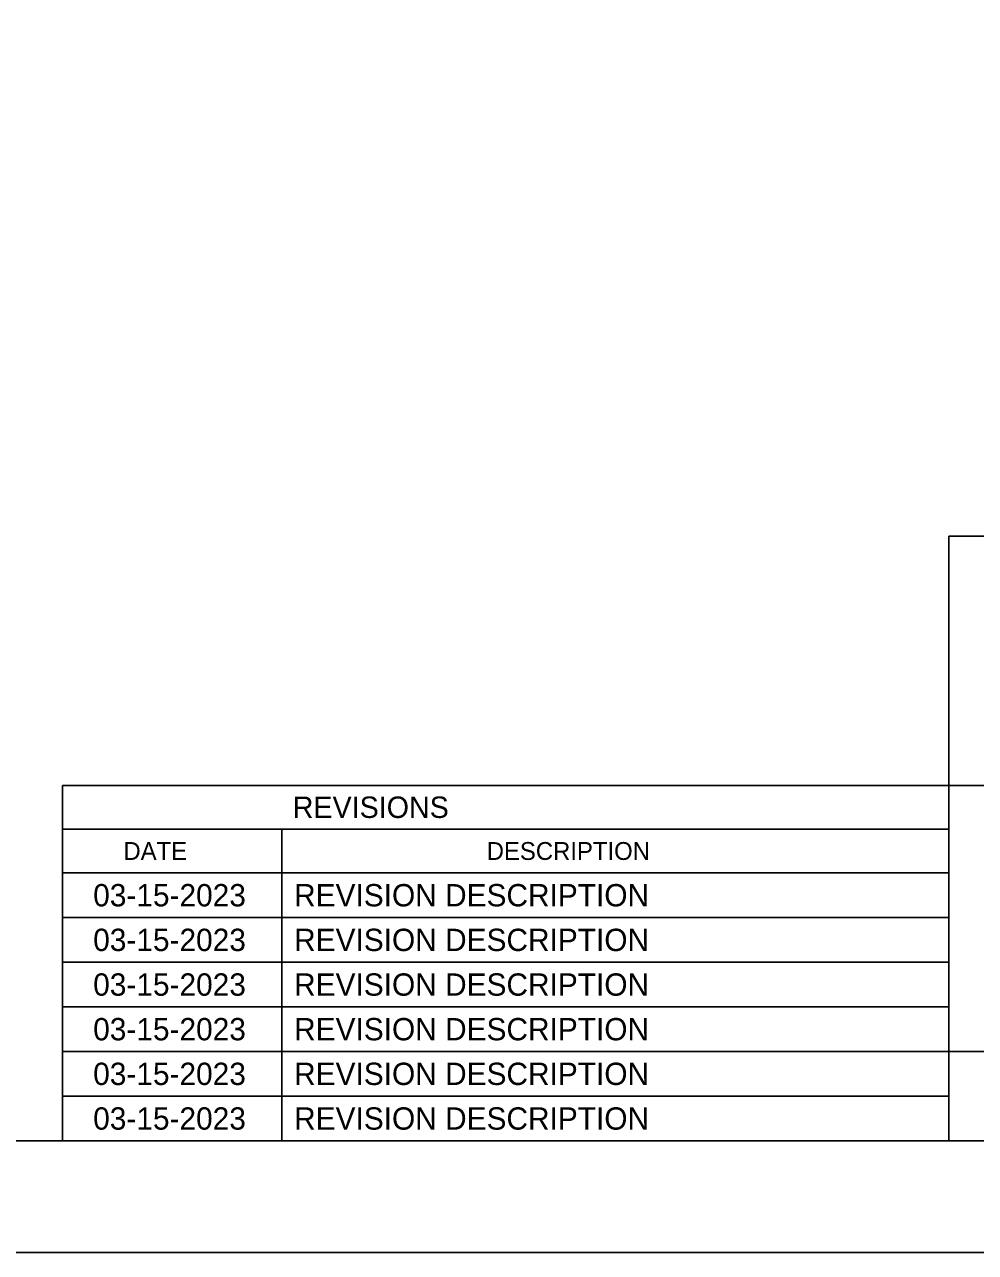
# Model space of a CAD drawing. Extents: x 0 to 2.83, y 0 to 1.83.
# Drawn here: x 2.0867 to 2.4416, y 0 to 0.4583 of the extents above; entities that cross this region are included whole.
import ezdxf

# ---------------------------------------------------------------- set-up
doc = ezdxf.new("R2010")
doc.units = 0
for name, color, linetype in [('SH_General_Details', 7, 'Continuous'), ('SH_General_Details_Sheet_Revision_Box-ILTollway', 7, 'Continuous'), ('SH_General_Details_Sheet_Revision_Text-ILTollway', 7, 'Continuous'), ('SH_Printer Plotting Border-ILTollway', 7, 'Continuous')]:
    doc.layers.add(name, color=color, linetype=linetype)

msp = doc.modelspace()

# ---------------------------------------------------------------- linework, layer by layer
at = {"layer": 'SH_General_Details'}
for p, q in [((2.43167, 0.04167), (2.43167, 0.2674)), ((2.79167, 0.2674), (2.43167, 0.2674)), ((2.79167, 0.17434), (2.43167, 0.17434)), ((2.79167, 0.075), (2.43167, 0.075))]:
    msp.add_line(p, q, dxfattribs=at)
msp.add_lwpolyline([(0.16667, 0.04167), (0.16667, 1.79167), (2.79167, 1.79167), (2.79167, 0.04167)], close=True, dxfattribs=at)
at = {"layer": 'SH_General_Details_Sheet_Revision_Box-ILTollway'}
for p, q in [((2.10084, 0.04167), (2.10084, 0.17434)), ((2.43167, 0.17434), (2.10084, 0.17434)), ((2.43167, 0.15802), (2.10084, 0.15802)), ((2.18272, 0.15802), (2.18272, 0.04167)), ((2.43167, 0.14167), (2.10084, 0.14167)), ((2.43167, 0.125), (2.10084, 0.125)), ((2.43167, 0.10833), (2.10084, 0.10833)), ((2.43167, 0.09167), (2.10084, 0.09167)), ((2.43167, 0.075), (2.10084, 0.075)), ((2.43167, 0.05833), (2.10084, 0.05833))]:
    msp.add_line(p, q, dxfattribs=at)
at = {"layer": 'SH_Printer Plotting Border-ILTollway'}
msp.add_lwpolyline([(0, 1.83328), (2.83333, 1.83328), (2.83333, 0), (0, 0)], close=True, dxfattribs=at)

# ---------------------------------------------------------------- texts
at = {"layer": 'SH_General_Details_Sheet_Revision_Box-ILTollway'}
for s, height, p in [('REVISIONS', 0.008, (2.18678, 0.16218)), ('DATE', 0.006667, (2.12358, 0.14651)), ('DESCRIPTION', 0.0066667, (2.25919, 0.14651))]:
    msp.add_text(s, height=height, rotation=0, dxfattribs=at).set_placement(p)
at = {"layer": 'SH_General_Details_Sheet_Revision_Text-ILTollway'}
for s, height, p in [('03-15-2023', 0.008333, (2.11229, 0.12917)), ('REVISION DESCRIPTION', 0.0083333, (2.18729, 0.12917)), ('03-15-2023', 0.008333, (2.11229, 0.1125)), ('REVISION DESCRIPTION', 0.0083333, (2.18729, 0.1125)), ('03-15-2023', 0.008333, (2.11229, 0.09583)), ('REVISION DESCRIPTION', 0.0083333, (2.18729, 0.09583)), ('03-15-2023', 0.008333, (2.11229, 0.07917)), ('REVISION DESCRIPTION', 0.0083333, (2.18729, 0.07917)), ('03-15-2023', 0.008333, (2.11229, 0.0625)), ('REVISION DESCRIPTION', 0.0083333, (2.18729, 0.0625)), ('03-15-2023', 0.008333, (2.11229, 0.04583)), ('REVISION DESCRIPTION', 0.0083333, (2.18729, 0.04583))]:
    msp.add_text(s, height=height, dxfattribs=at).set_placement(p)

doc.saveas('drawing.dxf')
